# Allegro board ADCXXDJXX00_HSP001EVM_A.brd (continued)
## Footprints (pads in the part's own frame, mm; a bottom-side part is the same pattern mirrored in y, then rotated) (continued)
DBV5
  rect 1.27x0.508 smd: 1(-1.1,0.95) 2(-1.1,0) 3(-1.1,-0.95) 4(1.1,-0.95) 5(1.1,0.95)
DIODE_MBRB2515L
  rect 3.048x1.016 smd: 1(5.652,-2.54) 3(5.652,2.54)
  round 0.013 smd: 2(5.652,0)
  rect 8.382x10.668 smd: 4(-5.652,0)
DIODE_SM_1N4148W
  rect 0.889x0.94 smd: 1(-1.575,0) 2(1.575,0)
HDR_THVT_1X2_100_M
  rect 1.473x1.473 hole 0.965: 1(0,0)
  round 1.473 hole 0.965: 2(0,-2.54)
HDR_THVT_1X3_100_M
  rect 1.575x1.575 hole 1.016: 1(0,0)
  round 1.575 hole 1.016: 2(0,-2.54) 3(0,-5.08)
HDR_THVT_1X4_100_M
  rect 1.473x1.473 hole 0.965: 1(0,0)
  round 1.473 hole 0.965: 2(0,-2.54) 3(0,-5.08) 4(0,-7.62)
HDR_THVT_2X4_100_M
  rect 1.473x1.473 hole 0.965: 1(0,0)
  round 1.473 hole 0.965: 2(2.54,0) 3(0,-2.54) 4(2.54,-2.54) 5(0,-5.08) 6(2.54,-5.08) 7(0,-7.62) 8(2.54,-7.62)
IND_0603
  rect 0.635x1.016 smd: 1(-0.635,0) 2(0.635,0)
IND_SM_XFL4015
  rect 0.991x3.404 smd: 1(-1.181,0) 2(1.181,0)
LED_0603
  rect 0.762x0.813 smd: 1(-0.787,0) 2(0.787,0)
LED_0805
  rect 1.422x1.524 smd: 1(-1.143,0) 2(1.143,0)
MFG125_PLATED
  round 3.556 hole 3.175: 1(0,0)
MSOP_8_118X118_0P65MM
  rect 1.45x0.46 smd: 1(-2.2,0.975) 2(-2.2,0.325) 3(-2.2,-0.325) 4(-2.2,-0.975) 5(2.2,-0.975) 6(2.2,-0.325) 7(2.2,0.325) 8(2.2,0.975)
PROBE_POINT_30PAD
  round 0.762 smd: 1(0,0)
QFN40_RTA_RTB_RHA
  custom 0.076x0.076 smd: 1(-3.025,2.25) 2(-3.025,1.75) 3(-3.025,1.25) 4(-3.025,0.75) 5(-3.025,0.25) 6(-3.025,-0.25) 7(-3.025,-0.75) 8(-3.025,-1.25) 9(-3.025,-1.75) 10(-3.025,-2.25) 11(-2.25,-3.025) 12(-1.75,-3.025) 13(-1.25,-3.025) 14(-0.75,-3.025) 15(-0.25,-3.025) 16(0.25,-3.025) 17(0.75,-3.025) 18(1.25,-3.025) 19(1.75,-3.025) 20(2.25,-3.025) 21(3.025,-2.25) 22(3.025,-1.75) 23(3.025,-1.25) 24(3.025,-0.75) 25(3.025,-0.25) 26(3.025,0.25) 27(3.025,0.75) 28(3.025,1.25) 29(3.025,1.75) 30(3.025,2.25) 31(2.25,3.025) 32(1.75,3.025) 33(1.25,3.025) 34(0.75,3.025) 35(0.25,3.025) 36(-0.25,3.025) 37(-0.75,3.025) 38(-1.25,3.025) 39(-1.75,3.025) 40(-2.25,3.025)
  rect 4.572x4.572 smd: 41(0,0)
QFN_7_2MMX2MM
  rect 0.6x0.25 smd: 1(-0.9,0.75)
  oval 0.6x0.25 smd: 2(-0.9,0.25) 3(-0.9,-0.25) 4(-0.9,-0.75)
  rect 1.5x0.3 smd: 5(0.45,-0.6) 6(0.45,0) 7(0.45,0.6)
QFN_20_197X197_0P65_RGW
  rect 0.991x0.356 smd: 1(-2.607,1.3) 2(-2.607,0.65) 3(-2.607,0) 4(-2.607,-0.65) 5(-2.607,-1.3) 11(2.607,-1.3) 12(2.607,-0.65) 13(2.607,0) 14(2.607,0.65) 15(2.607,1.3)
  rect 0.356x0.991 smd: 6(-1.3,-2.607) 7(-0.65,-2.607) 8(0,-2.607) 9(0.65,-2.607) 10(1.3,-2.607) 16(1.3,2.607) 17(0.65,2.607) 18(0,2.607) 19(-0.65,2.607) 20(-1.3,2.607)
  rect 3.15x3.15 smd: 21(0,0)
QFN_20_199X199_0P65MM
  rect 0.991x0.356 smd: 1(-2.4,1.3) 2(-2.4,0.65) 3(-2.4,0) 4(-2.4,-0.65) 5(-2.4,-1.3) 11(2.4,-1.3) 12(2.4,-0.65) 13(2.4,0) 14(2.4,0.65) 15(2.4,1.3)
  rect 0.356x0.991 smd: 6(-1.3,-2.4) 7(-0.65,-2.4) 8(0,-2.4) 9(0.65,-2.4) 10(1.3,-2.4) 16(1.3,2.4) 17(0.65,2.4) 18(0,2.4) 19(-0.65,2.4) 20(-1.3,2.4)
  rect 3.15x3.15 smd: 21(0,0)
QFN_64_0P50MM_RGC_FT2232HQ
  custom 0.076x0.076 smd: 1(-4.58,3.753) 2(-4.58,3.252) 3(-4.58,2.752) 4(-4.58,2.252) 5(-4.58,1.751) 6(-4.58,1.251) 7(-4.58,0.751) 8(-4.58,0.25) 9(-4.58,-0.25) 10(-4.58,-0.751) 11(-4.58,-1.251) 12(-4.58,-1.751) 13(-4.58,-2.252) 14(-4.58,-2.752) 15(-4.58,-3.252) 16(-4.58,-3.753) 17(-3.753,-4.58) 18(-3.252,-4.58) 19(-2.752,-4.58) 20(-2.252,-4.58) 21(-1.751,-4.58) 22(-1.251,-4.58) 23(-0.751,-4.58) 24(-0.25,-4.58) 25(0.25,-4.58) 26(0.751,-4.58) 27(1.251,-4.58) 28(1.751,-4.58) 29(2.252,-4.58) 30(2.752,-4.58) 31(3.252,-4.58) 32(3.753,-4.58) 33(4.58,-3.753) 34(4.58,-3.252) 35(4.58,-2.752) 36(4.58,-2.252) 37(4.58,-1.751) 38(4.58,-1.251) 39(4.58,-0.751) 40(4.58,-0.25) 41(4.58,0.25) 42(4.58,0.751) 43(4.58,1.251) 44(4.58,1.751) 45(4.58,2.252) 46(4.58,2.752) 47(4.58,3.252) 48(4.58,3.753) 49(3.753,4.58) 50(3.252,4.58) 51(2.752,4.58) 52(2.252,4.58) 53(1.751,4.58) 54(1.251,4.58) 55(0.751,4.58) 56(0.25,4.58) 57(-0.25,4.58) 58(-0.751,4.58) 59(-1.251,4.58) 60(-1.751,4.58) 61(-2.252,4.58) 62(-2.752,4.58) 63(-3.252,4.58) 64(-3.753,4.58)
  rect 4.318x4.318 smd: 65(0,0)
QFN_64_360X360_0P50MM_PWRPAD
  oval 1.016x0.305 smd: 1(-4.58,3.753) 2(-4.58,3.252) 3(-4.58,2.752) 4(-4.58,2.252) 5(-4.58,1.751) 6(-4.58,1.251) 7(-4.58,0.751) 8(-4.58,0.25) 9(-4.58,-0.25) 10(-4.58,-0.751) 11(-4.58,-1.251) 12(-4.58,-1.751) 13(-4.58,-2.252) 14(-4.58,-2.752) 15(-4.58,-3.252) 16(-4.58,-3.753) 33(4.58,-3.753) 34(4.58,-3.252) 35(4.58,-2.752) 36(4.58,-2.252) 37(4.58,-1.751) 38(4.58,-1.251) 39(4.58,-0.751) 40(4.58,-0.25) 41(4.58,0.25) 42(4.58,0.751) 43(4.58,1.251) 44(4.58,1.751) 45(4.58,2.252) 46(4.58,2.752) 47(4.58,3.252) 48(4.58,3.753)
  oval 0.305x1.016 smd: 17(-3.753,-4.58) 18(-3.252,-4.58) 19(-2.752,-4.58) 20(-2.252,-4.58) 21(-1.751,-4.58) 22(-1.251,-4.58) 23(-0.751,-4.58) 24(-0.25,-4.58) 25(0.25,-4.58) 26(0.751,-4.58) 27(1.251,-4.58) 28(1.751,-4.58) 29(2.252,-4.58) 30(2.752,-4.58) 31(3.252,-4.58) 32(3.753,-4.58) 49(3.753,4.58) 50(3.252,4.58) 51(2.752,4.58) 52(2.252,4.58) 53(1.751,4.58) 54(1.251,4.58) 55(0.751,4.58) 56(0.25,4.58) 57(-0.25,4.58) 58(-0.751,4.58) 59(-1.251,4.58) 60(-1.751,4.58) 61(-2.252,4.58) 62(-2.752,4.58) 63(-3.252,4.58) 64(-3.753,4.58)
  rect 7.366x7.366 smd: 65(0,0)
SMA_SMEL_373X312
  rect 0.635x5.08 smd: 1(0,-2.54)
  rect 2.286x5.08 smd: 2(-4.445,-2.54) 3(4.445,-2.54) 4(-4.445,-2.54) 5(4.445,-2.54)
SMA_THVT_312X312
  round 2.337 hole 1.575: 1(0,0)
  round 2.464 hole 1.702: 2(-2.54,2.54) 3(2.54,2.54) 4(2.54,-2.54) 5(-2.54,-2.54)
SMA_THVT_SMT_250X250
  round 0.787 smd: 1(0,0)
  round 1.829 hole 1.499: 2(-2.54,-2.54) 3(2.54,-2.54) 4(2.54,2.54) 5(-2.54,2.54)
SMD_JUMPER_L_0402
  rect 0.508x0.508 smd: 1(-0.508,0) 2(0.508,0) 3(0.508,1.016)
SMP_B120
  rect 0.508x1.321 smd: 1(0,-3.1)
  custom 1.3x1.3 smd: 2(0,0)
SO_8_207X207_50
  rect 1.702x0.66 smd: 1(-3.645,1.905) 2(-3.645,0.635) 3(-3.645,-0.635) 4(-3.645,-1.905) 5(3.645,-1.905) 6(3.645,-0.635) 7(3.645,0.635) 8(3.645,1.905)
SOIC_8_197X157_50
  rect 2.159x0.61 smd: 1(-2.44,1.905) 2(-2.44,0.635) 3(-2.44,-0.635) 4(-2.44,-1.905) 5(2.44,-1.905) 6(2.44,-0.635) 7(2.44,0.635) 8(2.44,1.905)
SON_Q5B_8
  rect 1.372x0.711 smd: 1(-2.767,1.905) 2(-2.767,0.635) 3(-2.767,-0.635) 4(-2.767,-1.905) 5(2.767,-1.905) 6(2.767,-0.635) 7(2.767,0.635) 8(2.767,1.905)
SOT_5_120X69_37
  rect 0.61x1.524 smd: 1(-0.95,-1.75) 2(0,-1.75) 3(0.95,-1.75) 4(0.95,1.75) 5(-0.95,1.75)
SOT_5_120X69_57
  rect 0.61x1.524 smd: 1(-0.95,-1.35) 2(0,-1.35) 3(0.95,-1.35) 4(0.95,1.35) 5(-0.95,1.35)
SOT_23_MMBT3904
  rect 0.991x1.397 smd: 1(-0.953,-1.105) 2(0.953,-1.105) 3(0,1.105)
TANT_B
  rect 2.032x2.286 smd: 1(-1.524,0) 2(1.524,0)
TFMR_5_150X150_50
  rect 1.651x0.762 smd: 1(1.587,1.27) 2(1.587,0) 3(1.587,-1.27) 4(-1.587,-1.27) 6(-1.587,1.27)
TP_THVT_100_RND
  round 2.54 hole 1.016: 1(0,0)
TP_THVT_125_RND_063D
  round 2.362 hole 1.6: 1(0,0)
TSSOP_16_201X177_26
  rect 1.6x0.35 smd: 1(-2.825,2.275) 2(-2.825,1.625) 3(-2.825,0.975) 4(-2.825,0.325) 5(-2.825,-0.325) 6(-2.825,-0.975) 7(-2.825,-1.625) 8(-2.825,-2.275) 9(2.825,-2.275) 10(2.825,-1.625) 11(2.825,-0.975) 12(2.825,-0.325) 13(2.825,0.325) 14(2.825,0.975) 15(2.825,1.625) 16(2.825,2.275)
unnamed#2
  round 1.016 smd: 1(0,0)
unnamed#3
  round 0.762 smd: (0,0)
VCXO_6_CUSTOM
  rect 5.74x1.956 smd: 1(-3.81,2.54) 2(-3.81,0) 3(-3.81,-2.54) 4(3.81,-2.54) 5(3.81,0) 6(3.81,2.54)
WSON_14_4MMX4MM_0P5
  rect 0.61x0.254 smd: 1(-1.9,1.5) 2(-1.9,1) 3(-1.9,0.5) 4(-1.9,0) 5(-1.9,-0.5) 6(-1.9,-1) 7(-1.9,-1.5) 8(1.9,-1.5) 9(1.9,-1) 10(1.9,-0.5) 11(1.9,0) 12(1.9,0.5) 13(1.9,1) 14(1.9,1.5)
  rect 2.6x3 smd: 15(0,0)
XTAL_2_SM_126X197
  rect 1.9x2.4 smd: 1(-2.05,0) 2(2.05,0)

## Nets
1.4V: C211.1 C212.1 C213.1 L4.2 R158.2 R160.1 R164.1 R167.2 SJP3.1(PIN1) SJP4.1(PIN1) TP17.1 U17.4(VOS) U20.5(IN1) U20.6(IN2) U20.7(IN3) U20.8(IN4)
5.0V_IN: D13.4 F1.1 J37.1 Q3.5(D5) Q3.6(D6) Q3.7(D7) Q3.8(D8) TP12.1(TP) U13.5(VIN)
5VIN: C196.1 C198.1 C209.1 C215.1 C225.1 C238.1 F1.2 Q3.1(S1) Q3.2(S2) Q3.3(S3) R148.1 U14.1(EN) U14.7(IN) U17.1(EN) U17.7(IN) U21.13(EN) U21.15(IN2) U21.16(IN1) U22.13(EN) U22.15(IN2) U22.16(IN1)
+2.2V: C206.1 C207.1 C208.1 C210.1 L3.2 R150.1 R152.1 SJP2.1(PIN1) SJP3.3(PIN3) TP15.1(TP) U14.4(VOS) U16.15(IN3) U16.16(IN2) U16.17(IN1)
+3.3V_LMX: C100.1 C101.1 C102.2 C103.1 C106.1 C107.2 C113.1 C114.2 C242.1 C243.1 C244.1 C245.1 FB22.2 R46.2 TP24.1 U3.7(VCCDIG) U3.11(VCCCP) U3.15(VCCDIV) U3.21(VCCBUF) U3.26(VCCDBLR) U3.37(VCCVCO)
+3.3V_LMXRF: C99.1 C105.1 C247.1 C248.1 FB23.2 R44.2 R45.2 R48.2 R49.2 TP27.1
+3.3VCLK: C229.1 C230.1 C233.1 C234.1 FB1.2 FB2.1 FB3.1 FB4.1 FB5.1 FB6.1 FB10.1 FB11.1 FB20.2 R82.1 R88.1 R96.2 SJP1.3(PIN3) TP22.1
GND: C1.2 C2.2 C3.1 C4.1 C14.1 C24.1 C41.2 C42.2 C43.2 C54.2 C55.2 C56.2 C57.2 C58.2 C59.2 C60.2 C61.2 C62.2 C63.2 C64.2 C65.2 C66.2 C67.2 C68.2 C69.2 C70.2 C71.2 C72.2 C73.2 C74.2 C75.2 C76.2 C77.2 C78.2 C79.2 C80.2 C81.2 C82.2 C83.2 C84.2 C85.2 C86.2 C87.2 C88.2 C89.2 C90.2 C91.2 C92.2 C93.2 C94.2 C95.2 C96.2 C99.2 C100.2 C101.2 C102.1 C103.2 C104.1 C105.2 C106.2 C107.1 C109.2 C111.1 C112.1 C113.2 C114.1 C115.1 C116.1 C117.1 C118.1 C119.2 C121.2 C122.2 C130.2 C132.2 C137.1 C138.1 C139.1 C140.1 C141.1 C146.1 C152.1 C154.1 C155.1 C156.1 C157.2 C158.2 C159.2 C160.1 C161.1 C162.1 C163.2 C164.2 C165.2 C166.2 C167.1 C168.2 C169.2 C170.2 C171.2 C172.2 C173.2 C174.2 C175.2 C176.2 C177.2 C178.2 C179.2 C180.2 C181.2 C182.2 C183.2 C184.2 C185.2 C186.2 C187.2 C188.2 C189.2 C190.2 C191.2 C192.2 C193.2 C194.2 C195.2 C196.2 C198.2 C200.2 C201.2 C202.2 C203.2 C204.2 C205.2 C206.2 C207.2 C208.2 C209.2 C210.2 C211.2 C212.2 C213.2 C214.2 C215.2 C217.2 C218.2 C219.2 C220.2 C221.2 C222.2 C223.2 C224.2 C225.2 C226.2 C227.2 C228.2 C229.2 C230.2 C233.2 C234.2 C235.2 C236.2 C237.2 C238.2 C239.2 C240.2 C241.2 C242.2 C243.2 C244.2 C245.2 C246.2 C247.2 C248.2 D2.2(CATHODE) D3.2(CATHODE) D4.2(CATHODE) D5.2(CATHODE) D6.2(CATHODE) D8.2(CATHODE) D13.1 D13.3 FB16.2 FB17.2 FB18.2 FB19.2 J1.2(SHIELD1) J1.3(SHIELD2) J1.4(SHIELD3) J1.5(SHIELD4) J2.2(GND#2) J2.3(GND#3) J2.4(GND#4) J2.5(GND#5) J3.2(SHIELD1) J3.3(SHIELD2) J3.4(SHIELD3) J3.5(SHIELD4) J4.2(SHIELD1) J4.3(SHIELD2) J4.4(SHIELD3) J4.5(SHIELD4) J5.2(GND#2) J5.3(GND#3) J5.4(GND#4) J5.5(GND#5) J6.2(SHIELD1) J6.3(SHIELD2) J6.4(SHIELD3) J6.5(SHIELD4) J14.2(GND#2) J14.3(GND#3) J14.4(GND#4) J14.5(GND#5) J15.2(GND#2) J15.3(GND#3) J15.4(GND#4) J15.5(GND#5) J18.2(GND#2) J18.3(GND#3) J18.4(GND#4) J18.5(GND#5) J20.2(SHIELD1) J22.2(GND#2) J22.3(GND#3) J22.4(GND#4) J22.5(GND#5) J23.2(SHIELD1) J23.3(SHIELD2) J23.4(SHIELD3) J23.5(SHIELD4) J24.2(SHIELD1) J24.3(SHIELD2) J24.4(SHIELD3) J24.5(SHIELD4) J25.A1 J25.A4 J25.A5 J25.A8 J25.A9 J25.A12 J25.A13 J25.A16 J25.A17 J25.A20 J25.A24 J25.A25 J25.A28 J25.A29 J25.A32 J25.A33 J25.A36 J25.A37 J25.A40 J25.B3 J25.B6 J25.B7 J25.B10 J25.B11 J25.B14 J25.B15 J25.B18 J25.B26 J25.B27 J25.B30 J25.B31 J25.B34 J25.B35 J25.B38 J25.B39 J25.C5 J25.C8 J25.C24 J25.C25 J25.C28 J25.C29 J25.C32 J25.C33 J25.C36 J25.C38 J25.C40 J25.D3 J25.D6 J25.D25 J25.D28 J25.D37 J25.D39 J25.E26 J25.E29 J25.E32 J25.E35 J25.E38 J25.E40 J25.F27 J25.F30 J25.F33 J25.F36 J25.F39 J25.G5 J25.G8 J25.G11 J25.G14 J25.G26 J25.G29 J25.G32 J25.G35 J25.G38 J25.G40 J25.H27 J25.H30 J25.H33 J25.H36 J25.H39 J25.J29 J25.J32 J25.J35 J25.J38 J25.J40 J25.K30 J25.K33 J25.K36 J25.K39 J25.L30 J25.L31 J25.L34 J25.L35 J25.L38 J25.L39 J25.M1 J25.M29 J25.M32 J25.M33 J25.M36 J25.M37 J25.M40 J25.Y4 J25.Y5 J25.Y8 J25.Y9 J25.Y12 J25.Y13 J25.Y16 J25.Y17 J25.Y20 J25.Y21 J25.Y24 J25.Y25 J25.Y28 J25.Y29 J25.Y32 J25.Y33 J25.Y36 J25.Y37 J25.Y40 J25.Z2 J25.Z3 J25.Z7 J25.Z10 J25.Z11 J25.Z14 J25.Z15 J25.Z18 J25.Z19 J25.Z22 J25.Z23 J25.Z26 J25.Z27 J25.Z30 J25.Z31 J25.Z34 J25.Z35 J25.Z38 J25.Z39 J28.3 J31.5(GND) J31.6(GND1) J31.7(GND2) J31.8(GND3) J31.9(GND4) J37.2 J37.3 J38.2(GND#2) J38.3(GND#3) J38.4(GND#4) J38.5(GND#5) JP5.1 JP7.2 JP8.2 JP9.2 MT1.1 MT2.1 R11.2 R12.2 R17.2 R18.2 R21.2 R23.2 R26.2 R31.2 R32.2 R33.2 R51.1 R52.1 R53.1 R56.2 R57.2 R58.2 R61.2 R62.2 R63.2 R64.2 R65.2 R66.2 R68.2 R71.2 R72.2 R74.2 R75.2 R78.2 R79.2 R80.2 R81.2 R84.2 R85.2 R86.2 R87.2 R89.2 R90.2 R92.2 R93.2 R94.2 R95.2 R99.2 R106.2 R108.2 R109.2 R122.1 R153.2 R154.1 R155.1 R156.1 R157.1 R166.2 R168.2 R169.2 R170.1 R171.1 R172.1 R173.1 R174.1 R175.1 R176.1 R177.1 R183.1 R184.2 R185.2 R187.2 R188.2 R189.2 SJP1.1(PIN1) SJP2.3(PIN3) T1.2(SECONDARY_CT) T1.4(PRIMARY) T2.4(PRIMARY) TP13.1(TP) TP16.1(TP) TP18.1(TP) TP21.1(TP) TP28.1(TP) TP29.1(TP) TP30.1(TP) U1.A1(AGND#A1) U1.A2(AGND#A2) U1.A3(AGND#A3) U1.A6(AGND#A6) U1.A7(AGND#A7) U1.A12(DGND#A12) U1.B2(AGND#B2) U1.B3(AGND#B3) U1.B4(AGND#B4) U1.B5(AGND#B5) U1.B6(AGND#B6) U1.B7(AGND#B7) U1.B12(DGND#B12) U1.C6(AGND#C6) U1.D1(AGND#D1) U1.D6(AGND#D6) U1.D9(DGND#D9) U1.D10(DGND#D10) U1.E1(AGND#E1) U1.E6(AGND#E6) U1.F2(AGND#F2) U1.F3(AGND#F3) U1.F6(AGND#F6) U1.F9(DGND#F9) U1.F10(DGND#F10) U1.G2(AGND#G2) U1.G3(AGND#G3) U1.G6(AGND#G6) U1.G9(DGND#G9) U1.G10(DGND#G10) U1.H1(AGND#H1) U1.H6(AGND#H6) U1.J1(AGND#J1) U1.J6(AGND#J6) U1.J9(DGND#J9) U1.J10(DGND#J10) U1.L2(AGND#L2) U1.L3(AGND#L3) U1.L4(AGND#L4) U1.L5(AGND#L5) U1.L6(AGND#L6) U1.L7(AGND#L7) U1.L12(DGND#L12) U1.M1(AGND#M1) U1.M2(AGND#M2) U1.M3(AGND#M3) U1.M6(AGND#M6) U1.M7(AGND#M7) U1.M12(DGND#M12) U2.8(GND) U2.9(A0) U2.15(PWRPAD) U3.2(GND#2) U3.4(GND#4) U3.6(GND#6) U3.13(GND#13) U3.14(GND#14) U3.25(GND#25) U3.31(GND#31) U3.34(GND#34) U3.39(GND#39) U3.40(NC4) U3.41(PWRPAD) U4.65(DAP) U5.3(A2) U5.4(VSS) U6.2(GND) U7.3(GND) U8.1(GND#1) U8.5(GND#5) U8.10(AGND) U8.11(GND#11) U8.13(TEST) U8.15(GND#15) U8.25(GND#25) U8.35(GND#35) U8.47(GND#47) U8.51(GND#51) U8.65(PWRPAD) U9.5(VSS) U10.7(DIR3) U10.10(GND) U11.10(GND) U12.1(DIR1) U12.2(DIR2) U12.7(DIR3) U12.8(DIR4) U12.10(GND) U13.2(GND) U14.5(GND) U15.4(V-) U16.8(GND1) U16.18(GND2) U16.21(PWRPAD) U17.5(GND) U20.2(NC1) U20.3(NC2) U20.4(NC3) U20.12(GND) U20.13(NC4) U20.14(NC5) U20.17(NC6) U20.21(PAD) U21.7(GND) U21.21(PWRPAD) U22.7(GND) U22.21(PWRPAD) Y1.3(GND)
V3P3V: C226.1 C227.1 C228.1 FB20.1 FB21.1 U21.1(OUT1) U21.3(SENSE) U21.20(OUT2)
V3P3V_LMX: C239.1 C240.1 C241.1 FB22.1 FB23.1 U22.1(OUT1) U22.3(SENSE) U22.20(OUT2)
V11_OUT: C214.1 C216.1 C217.1 R161.1 R163.2 R165.1 U20.1(OUT1) U20.18(OUT2) U20.19(OUT3) U20.20(OUT4)
V19_SNS: FB16.1 FB17.1 R149.1 U16.1(OUT1) U16.2(SNS) U16.19(OUT2) U16.20(OUT3)
VBUS: C175.1 R111.1 U6.1(IN) U6.3(EN)
VBUSS: C173.1 FB14.1 U6.5(OUT)
VCCIN: C104.2 U3.10(VCCIN)
VDDD33: C1.1 C2.1 C41.1 C42.1 C43.1 C172.1 C180.1 C186.1 C187.1 C188.1 C189.1 C190.1 C192.1 C194.1 C236.1 C237.1 D1.1(ANODE) D7.1(ANODE) FB12.1 FB13.1 FB21.2 JP6.1(PIN1) R27.1 R28.1 R29.1 R30.1 R39.1 R41.1 R114.1 R115.1 R123.1 R124.1 R125.1 R130.1 TP23.1 U2.2(VDD) U7.5(VCC) U8.20(VCCIO#20) U8.31(VCCIO#31) U8.42(VCCIO#42) U8.56(VCCIO#56) U9.8(VCC) U10.1(DIR1) U10.2(DIR2) U10.8(DIR4) U10.16(VCCA) U11.1(DIR1) U11.2(DIR2) U11.7(DIR3) U11.8(DIR4) U11.16(VCCA) U12.16(VCCA) U15.8(V+)
VDDL19: C191.1 C193.1 C195.1 C200.1 C201.1 FB16.3 R132.1 TP11.1 U10.15(VCCB) U11.15(VCCB) U12.15(VCCB)
VINA: BALUN1.1(IN) J2.1(CENTER)
VINB: BALUN2.1(IN) J5.1(CENTER)
1P4V: L4.1 U17.6(SW)
1P8V_USB: C178.1 C179.1 C181.1 C182.1 C183.1 TP10.1 U8.12(VCORE#12) U8.37(VCORE#37) U8.49(VREGOUT) U8.64(VCORE#64)
2: D13.2
2P2V: L3.1 U14.6(SW)
3P3USB: C170.1 C171.1 FB13.2 TP7.1 U8.9(VPLL)
3P3V_RX: R105.2 TP5.1
3P3VAUX: C167.2 J25.D32 J28.4 U5.8(VCC)
12P0V_RX: J25.C35 J25.C37
ADBUS0: U8.16(ADBUS0) U10.3(A1)
ADBUS1: U8.17(ADBUS1) U10.4(A2)
ADBUS2: U8.18(ADBUS2) U10.5(A3)
ADBUS3: U8.19(ADBUS3) U10.6(A4)
ADC_CLK: R133.2 U1.F8(SCLK)
ADC_SCSB: R136.2 U1.E8(\\S\C\S\)
ADC_SDI: R134.2 U1.G8(SDI)
ADC_SDO: R135.2 U1.H8(SDO)
BDBUS0: R112.1 U8.26(BDBUS0)
BDBUS1: U7.2(A) U8.27(BDBUS1)
BDBUS2: R113.1 U8.28(BDBUS2)
BDBUS3: U7.1(O\E\) U8.29(BDBUS3)
BYPASS: FB18.1 FB19.1 R159.1 R163.1
CALTRG: J9.2 R23.1 U1.E7(CALTRG)
CDBUS0: R118.1 U8.38(CDBUS0)
CDBUS1: R119.1 U8.39(CDBUS1)
CDBUS2: R115.2 R120.1 U8.40(CDBUS2)
CDBUS3: R114.2 R121.1 U8.41(CDBUS3)
CE: JP5.2 R46.1 U3.1(CE)
CLK+: C49.1 R43.2 T2.1(SECONDARY_DOT)
CLK-: C52.1 R43.1 T2.3(SECONDARY)
CLK-IN: R67.1 R69.1 R70.2 R72.1 T1.6(PRIMARY_DOT)
CLK_+: C48.2 C49.2 C50.2 U1.F1(CLK+)
CLK_-: C51.2 C52.2 C53.2 U1.G1(CLK-)
CLKIN0: J38.1(CENTER) R186.1 R187.1
CLKIN0_N: C24.2 U4.38(CLKIN0N)
CLKIN0_P: C20.2 U4.37(CLKIN0P)
CLKIN1: C20.1 R186.2
CLKIN1_N: C136.2 C137.2 U4.35(CLKIN1N/FBCLKINN/FINN)
CLKIN1_P: C134.2 U4.34(CLKIN1P/FBCLKINP/FINP)
CLKINN: C136.1 R73.2 T1.3(SECONDARY)
CLKINP: C134.1 R68.1 R69.2 R73.1 T1.1(SECONDARY_DOT)
CLKLA_0N: R90.1 R127.1 U4.63(DCLKOUT12N)
CLKLA_0P: R89.1 R126.1 U4.62(DCLKOUT12P)
CLKM: C53.1 C135.2
CLKP: C48.1 C133.2
CP1: C128.1 C130.1 U4.32(CPOUT1) Y1.1(VC)
CP2: C131.1 C132.1 U4.46(CPOUT2)
CPOUT: C119.1 C120.1 R54.1 U3.12(CPOUT)
DA0+: C5.1 U1.E12(DA0+)
DA0-: C6.1 U1.F12(DA0-)
DA0_M: C6.2 J25.A11
DA0_P: C5.2 J25.A10
DA1+: C7.1 U1.C12(DA1+)
DA1-: C8.1 U1.D12(DA1-)
DA1_M: C8.2 J25.C7
DA1_P: C7.2 J25.C6
DA2+: C9.1 U1.A10(DA2+)
DA2-: C10.1 U1.A11(DA2-)
DA2_M: C10.2 J25.A7
DA2_P: C9.2 J25.A6
DA3+: C11.1 U1.A8(DA3+)
DA3-: C12.1 U1.A9(DA3-)
DA3_M: C12.2 J25.A3
DA3_P: C11.2 J25.A2
DA4+: C13.1 U1.E11(DA4+)
DA4-: C15.1 U1.F11(DA4-)
DA4_M: C15.2 J25.Y15
DA4_P: C13.2 J25.Y14
DA5+: C16.1 U1.C11(DA5+)
DA5-: C18.1 U1.D11(DA5-)
DA5_M: C18.2 J25.Y11
DA5_P: C16.2 J25.Y10
DA6+: C19.1 U1.B10(DA6+)
DA6-: C21.1 U1.B11(DA6-)
DA6_M: C21.2 J25.B9
DA6_P: C19.2 J25.B8
DA7+: C22.1 U1.B8(DA7+)
DA7-: C23.1 U1.B9(DA7-)
DA7_M: C23.2 J25.B5
DA7_P: C22.2 J25.B4
DB0+: C25.1 U1.H12(DB0+)
DB0-: C26.1 U1.G12(DB0-)
DB0_M: C26.2 J25.B12
DB0_P: C25.2 J25.B13
DB1+: C27.1 U1.K12(DB1+)
DB1-: C28.1 U1.J12(DB1-)
DB1_M: C28.2 J25.A14
DB1_P: C27.2 J25.A15
DB2+: C29.1 U1.M10(DB2+)
DB2-: C30.1 U1.M11(DB2-)
DB2_M: C30.2 J25.B16
DB2_P: C29.2 J25.B17
DB3+: C31.1 U1.M8(DB3+)
DB3-: C32.1 U1.M9(DB3-)
DB3_M: C32.2 J25.A18
DB3_P: C31.2 J25.A19
DB4+: C33.1 U1.H11(DB4+)
DB4-: C34.1 U1.G11(DB4-)
DB4_M: C34.2 J25.Z12
DB4_P: C33.2 J25.Z13
DB5+: C35.1 U1.K11(DB5+)
DB5-: C36.1 U1.J11(DB5-)
DB5_M: C36.2 J25.Z16
DB5_P: C35.2 J25.Z17
DB6+: C37.1 U1.L10(DB6+)
DB6-: C38.1 U1.L11(DB6-)
DB6_M: C38.2 J25.Y18
DB6_P: C37.2 J25.Y19
DB7+: C39.1 U1.L8(DB7+)
DB7-: C40.1 U1.L9(DB7-)
DB7_M: C40.2 J25.Y22
DB7_P: C39.2 J25.Y23
DCLKOUT2_N: C135.1 R75.1 U4.16(DCLKOUT2N)
DCLKOUT2_P: C133.1 R74.1 U4.15(DCLKOUT2P)
DCLKOUT6_N: C153.1 R95.1 U4.28(DCLKOUT6N)
DCLKOUT6_P: C151.1 R94.1 U4.27(DCLKOUT6P)
DCLKOUT8_N: R24.1 R57.1 U4.52(DCLKOUT8N)
DCLKOUT8_P: R22.1 R58.1 U4.51(DCLKOUT8P)
DCLKOUT10_N: C143.2 J24.1(CENTER)
DCLKOUT10_P: C142.2 J23.1(CENTER)
DCLKOUT10N: C143.1 R87.1 U4.55(DCLKOUT10N)
DCLKOUT10P: C142.1 R86.1 U4.54(DCLKOUT10P)
DDBUS0: U8.48(DDBUS0) U11.3(A1)
DDBUS1: U8.52(DDBUS1) U11.4(A2)
DDBUS2: U8.53(DDBUS2) U11.5(A3)
DDBUS3: U8.54(DDBUS3) U11.6(A4)
DDBUS4: U8.55(DDBUS4) U12.3(A1)
DDBUS5: U8.57(DDBUS5) U12.4(A2)
DDBUS6: U8.58(DDBUS6) U12.5(A3)
DDBUS7: U8.59(DDBUS7) U12.6(A4)
DEVCLKIN: J18.1(CENTER) T2.6(PRIMARY_DOT)
DM: R116.2 U8.7(DM)
DP: R117.2 U8.8(DP)
EE_ADDR0_RX: J25.C34 U5.1(A0)
EE_ADDR1_RX: J25.D35 U5.2(A1)
EECLK: R124.2 U8.62(EECLK) U9.2(CLK)
EECS: R125.2 U8.63(EECS) U9.1(CS)
EEDATA: R131.1 U8.61(EEDATA) U9.3(DI)
FMC_SCL: J25.C30 J28.2 U5.6(SCL)
FMC_SDA: J25.C31 J28.1 U5.5(SDA)
FPGA_JESD_CLK_A_N: J25.D5 R129.2
FPGA_JESD_CLK_A_P: J25.D4 R128.2
FPGA_JESD_CLK_B_N: J25.G7 R127.2
FPGA_JESD_CLK_B_P: J25.G6 R126.2
FPGA_JESD_CLK_C_N: J25.Z21 R24.2
FPGA_JESD_CLK_C_P: J25.Z20 R22.2
FPGA_JESD_SYSREFM: J25.G10 R60.2
FPGA_JESD_SYSREFP: J25.G9 R59.2
GTXCLKM: R64.1 R129.1 U4.2(DCLKOUT0N)
GTXCLKP: R65.1 R128.1 U4.1(DCLKOUT0P)
HSPC_PRSNT_M2C_L: J25.Z1 J30.1
INA+: BALUN1.3(O1) R1.1
INA-: BALUN1.2(O2) R4.1
INA_+: J1.1(CENTER) R180.1
INA_-: J3.1(CENTER) R179.1
INAN: R4.2 R179.2 U1.A5(INA-)
INAP: R1.2 R180.2 U1.A4(INA+)
INB+: BALUN2.2(O2) R6.1
INB-: BALUN2.3(O1) R9.1
INB_+: J4.1(CENTER) R151.1
INB_-: J6.1(CENTER) R162.1
INBN: R9.2 R162.2 U1.M5(INB-)
INBP: R6.2 R151.2 U1.M4(INB+)
JESD_SYSREFM: R60.1 R61.1 U4.4(SDCLKOUT1N)
JESD_SYSREFP: R59.1 R62.1 U4.3(SDCLKOUT1P)
LM95233_SMBCLK: R41.2 R112.2 U2.13(SMBCLK)
LM95233_SMBDAT: R39.2 R110.2 R113.2 U2.12(SMBDAT)
LMK04828_CSB: R120.2 TP36.1(TP) U4.18(\\C\S\)
LMK04828_SYNC: J25.J15 R97.2
LMK LOCKED: D5.1(ANODE) R102.1
LMK_CLKIN: J22.1(CENTER) R70.1 R71.1
LMK_LMX_CLK: R118.2 U3.16(SCK) U4.19(SCK)
LMK_LMX_DATA: R119.2 U3.17(SDI) U4.20(SDIO)
LMK_SDO: R99.1 R178.2 U4.5(RESET)
LMX_CLKB: C108.2 R52.2 R67.2
LMX_CLKM: C51.1 R45.1 U3.22(RFOUTAM)
LMX_CLKP: C50.1 R44.1 U3.23(RFOUTAP)
LMX_CSB: R121.2 U3.24(CSB)
LMX_OSCM: C151.2 C249.1 U3.9(OSCINM)
LMX_OSCP: C153.2 C250.1 U3.8(OSCINP)
LMX_SDO: R47.2 U8.43(CDBUS4)
MUX_OUT: R47.1 R50.2 U3.20(MUXOUT)
NCOA0: J7.2 R11.1 R138.2 U1.C7(NCOA0)
NCOA1: J7.4 R12.1 R139.2 U1.D7(NCOA1)
NCOB0: J7.6 R17.1 R140.2 U1.K7(NCOB0)
NCOB1: J7.8 R18.1 R141.2 U1.J7(NCOB1)
OSC_M: C250.2 R188.1 U4.41(OSCOUTN)
OSC_P: C249.2 R189.1 U4.40(OSCOUTP)
OSCI: C184.1 U8.2(OSCI) Y2.2
OSCINN: C150.2 C152.2 U4.44(OSCINN)
OSCINP: C145.2 C146.2 U4.43(OSCINP)
OSCN: C149.2 C150.1 R88.2 R93.1
OSCO: C185.1 U8.3(OSCO) Y2.1
OSCP: C144.2 C145.1 R82.2 R85.1
OVRA0: D12.1(ANODE) J25.G27 R143.2 U1.C8(OVRA0)
OVRA1: R144.2 U1.D8(OVRA1)
OVRB0: D9.1(ANODE) J25.D26 R145.2 U1.K8(OVRB0)
OVRB1: R146.2 U1.J8(OVRB1)
PD: J8.2 R21.1 U1.K6(PD)
PG: R149.2 SJP4.3(PIN3) U16.4(PG)
PG_RX1: J25.F1 J26.2 R104.2
PLL2 LOCKED: D6.1(ANODE) R103.1
PRSNT_M2C_L: J25.H2 R106.1
RFOUTB_M: C110.1 R49.1 U3.19(RFOUTBM)
RFOUTB_P: C108.1 R48.1 U3.18(RFOUTBP)
RFOUTBM: C110.2 J20.1(CENTER) R53.2
STAT 0: D3.1(ANODE) R100.1
STAT 1: D4.1(ANODE) R101.1
SYNC: R96.1 R97.1 R98.1 TP4.1(TP) U4.6(SYNC)
SYNC_N: J25.G13 R36.1
SYNC_P: J25.G12 R35.1
SYNC_SE: J25.H31 R25.1 R98.2
SYNCSE: R25.2 R26.1 U1.C2(SYNC~_SE)
SYS+: C45.2 U1.K1(SYSREF+)
SYS-: C47.2 U1.L1(SYSREF-)
SYSREF+: R76.1 R78.1 U4.13(SDCLKOUT3P)
SYSREF-: R77.1 R79.1 U4.14(SDCLKOUT3N)
SYSREFM: C47.1 R77.2 R80.1
SYSREFP: C45.1 R76.2 R81.1
TCRIT1: R28.2 R37.2 TP1.1(TP) U2.10(\\T\C\R\I\T\1)
TCRIT2: R27.2 TP2.1(TP) U2.11(\\T\C\R\I\T\2)
TCRIT3: R29.2 TP3.1(TP) U2.14(\\T\C\R\I\T\3)
TDI: J25.D30 J27.1
TDIODE+: J17.2 R40.2 U1.K2(TDIODE+)
TDIODE-: J17.1 R42.2 U1.K3(TDIODE-)
TDIODEN: C44.2 C46.2 Q1.2(E) R42.1 U2.5(D-)
TDIODEP: C44.1 R40.1 U2.7(D1+)
TDO: J25.D31 J27.2
TMSP+: J14.1(CENTER) R34.1
TMSP-: J15.1(CENTER) R38.1
TMSTP+: R34.2 R35.2 U1.B1(TMSTP+)
TMSTP-: R36.2 R38.2 U1.C1(TMSTP-)
U19_BYPASS: R158.1 R159.2
V_BUS: C174.1 C177.1 FB14.2 JP6.3(PIN3)
VA11: C54.1 C55.1 C56.1 C57.1 C58.1 C59.1 C60.1 C61.1 C62.1 C63.1 C64.1 C65.1 C66.1 C67.1 C68.1 C218.1 C219.1 C220.1 FB18.3 TP19.1 TP31.1 U1.C5(VA11#C5) U1.D2(VA11#D2) U1.D3(VA11#D3) U1.D5(VA11#D5) U1.E5(VA11#E5) U1.F5(VA11#F5) U1.G5(VA11#G5) U1.H5(VA11#H5) U1.J2(VA11#J2) U1.J3(VA11#J3) U1.J5(VA11#J5) U1.K5(VA11#K5)
VA19: C69.1 C70.1 C71.1 C72.1 C73.1 C74.1 C75.1 C76.1 C77.1 C78.1 C79.1 C80.1 C81.1 C82.1 C83.1 C202.1 C203.1 C204.1 C205.1 FB17.3 R13.1 R14.1 R15.1 R16.1 R19.1 R20.1 TP14.1 TP32.1 U1.C4(VA19#C4) U1.D4(VA19#D4) U1.E2(VA19#E2) U1.E3(VA19#E3) U1.E4(VA19#E4) U1.F4(VA19#F4) U1.G4(VA19#G4) U1.H2(VA19#H2) U1.H3(VA19#H3) U1.H4(VA19#H4) U1.J4(VA19#J4) U1.K4(VA19#K4)
VADJ_RX: J25.E39 J25.F40 J25.G39 J25.H40 R104.1 R107.1 TP6.1
VBIAS_VCO: C116.2 U3.3(VBIASVCO)
VBIASBANK: C109.1 C111.2 U3.27(VBIASBANK)
VD11: C84.1 C85.1 C86.1 C87.1 C88.1 C89.1 C90.1 C91.1 C92.1 C93.1 C94.1 C95.1 C96.1 C222.1 C223.1 C224.1 FB19.3 TP20.1 TP33.1 U1.C9(VD11#C9) U1.C10(VD11#C10) U1.E9(VD11#E9) U1.E10(VD11#E10) U1.G7(VD11#G7) U1.H7(VD11#H7) U1.H9(VD11#H9) U1.H10(VD11#H10) U1.K9(VD11#K9) U1.K10(VD11#K10)
VIO_B_M2C_RX: J25.J39 J25.K40 R107.2
VPHY: C168.1 C169.1 FB12.2 U8.4(VPHY)
VREF_VCO1: C112.2 U3.29(VREFVCO#29)
VREF_VCO2: C115.2 U3.36(VREFVCO#36)
VREG_VCO: C117.2 U3.38(VREGVCO)
VREGIN: C176.1 JP6.2(PIN2) U8.50(VREGIN)
VTUNE: C122.1 R55.2 U3.35(VTUNE)
Y1_N: R91.1 R92.1 Y1.4(OUT_N)
Y1_P: R83.1 R84.1 Y1.5(OUT_P)
YO1_N: C149.1 R91.2
YO1_P: C144.1 R83.2
N18340257: D8.1(ANODE) R148.2
N19631466: C235.1 U21.14(NR)
N19631491: R173.2 U21.8(1P6V)
N19631493: R171.2 U21.11(0P2V)
N19631495: R170.2 U21.12(0P1V)
N19631505: R172.2 U21.10(0P4V)
N19884870: C138.2 C139.2 C140.2 C141.2 FB1.1 Y1.6(VDD)
N19884947: SJP1.2(PIN2) Y1.2(NC)
N19887754: FB8.2 U4.42(VCC8_OSCIN)
N19887756: C160.2 C161.2 C162.2 FB6.2 FB7.1 FB8.1 FB9.1 U4.47(VCC10_PLL2)
N19887760: C165.1 FB10.2 U4.53(VCC11_CG3)
N19887762: C166.1 FB11.2 U4.64(VCC12_CG0)
N19887789: R102.2 U4.31(STATUS_LD1)
N19887795: R103.2 U4.48(STATUS_LD2)
N19887804: R101.2 U4.59(CLKIN_SEL1)
N19887822: R100.2 U4.58(CLKIN_SEL0)
N19887828: C163.1 U4.12(LDOBYP2)
N19887830: C164.1 U4.11(LDOBYP1)
N19887836: C154.2 C155.2 C156.2 FB2.2 U4.10(VCC1_VCO) U4.33(VCC5_DIG) U4.36(VCC6_PLL1)
N19887876: FB7.2 U4.39(VCC7_OSCOUT)
N19887878: FB9.2 U4.45(VCC9_CP2)
N19887910: C158.1 FB4.2 U4.21(VCC3_SYSREF)
N19887912: C157.1 FB3.2 U4.17(VCC2_CG1)
N19887930: C159.1 FB5.2 U4.26(VCC4_CG2)
N19955835: Q3.4(G) U13.4(GATE)
N20042801: R155.2 U16.7(200MV)
N20043120: R154.2 U16.6(100MV)
N20043460: R156.2 U16.9(400MV)
N20043630: R157.2 U16.10(800MV)
N20101312: R152.2 R153.1 U14.3(FB)
N20101373: R150.2 U14.2(PG)
N20111831: R160.2 R166.1 U17.3(FB)
N20111884: R164.2 U17.2(PG)
N20113519: C216.2 R165.2 R169.1
N20150497: SJP2.2(PIN2) U16.14(EN)
N20151052: SJP3.2(PIN2) U20.10(BIAS)
N20220969: C246.1 U22.14(NR)
N20220990: R177.2 U22.8(1P6V)
N20220992: R175.2 U22.11(0P2V)
N20220994: R174.2 U22.12(0P1V)
N20221006: R176.2 U22.10(0P4V)
N20234062: C118.2 U3.33(VBIASVARAC)
N20239082: R51.2 U3.30(REXT)
N20251064: C120.2 R56.1
N20251377: C121.1 R54.2 R55.1
N20258125: D2.1(ANODE) R50.1
N20381922: R130.2 U8.14(RESET)
N20381931: R122.2 U8.6(REF)
N20382261: C221.1 U20.15(SS)
N20382558: R123.2 R131.2 U9.4(DO)
N20382827: J31.3(D+) R117.1
N20382847: J31.2(D-) R116.1
N20392160: J31.1(VBUS) R111.2
N20393078: D7.2(CATHODE) R109.1
N20399374: R161.2 R168.1 U20.16(FB/SNS)
N20400206: SJP4.2(PIN2) U20.11(EN)
N20442573: J7.1 R13.2
N20442576: J7.3 R14.2
N20442579: J7.5 R15.2
N20442582: J7.7 R16.2
N20446174: TP26.1(TP) U1.C3(BG)
N20447902: D1.2(CATHODE) R37.1
N20452911: C46.1 Q1.1(B) Q1.3(C) U2.6(D2+)
N20475697: R138.1 U11.14(B1)
N20475701: R139.1 U11.13(B2)
N20475713: R140.1 U11.12(B3)
N20475725: R141.1 U11.11(B4)
N20475883: R142.1 U11.9(OEB)
N20476138: JP8.1 R142.2
N20477206: R133.1 U10.14(B1)
N20477210: R134.1 U10.13(B2)
N20477222: R135.1 U10.12(B3)
N20477234: R132.2 R136.1 U10.11(B4)
N20477392: R137.1 U10.9(OEB)
N20477396: JP7.1 R137.2
N20478124: R110.1 U7.4(Y)
N20479286: R143.1 U12.14(B1)
N20479288: R144.1 U12.13(B2)
N20479290: R145.1 U12.12(B3)
N20479292: R146.1 U12.11(B4)
N20479340: R147.1 U12.9(OEB)
N20479396: JP9.1 R147.2
N20523656: TP25.1(TP) U1.F7(CALSTAT)
N20560674: J25.C39 J25.D36 J25.D38 J25.D40 R105.1
N20560927: J25.D1 J26.1
N20597236: J30.2 R108.1
N20599204: R183.2 U16.5(50MV)
N20601243: D10.1(ANODE) U15.7(OUTB)
N20601382: D11.1(ANODE) U15.1(OUTA)
N20601403: D10.2(CATHODE) R185.1
N20601859: D11.2(CATHODE) R32.1
N20602433: C14.2 D9.2(CATHODE) R184.1 U15.5(INB+)
N20603216: C3.2 D12.2(CATHODE) R31.1 U15.3(INA+)
N20603624: C4.2 R30.2 R33.1 U15.2(INA-) U15.6(INB-)
N20606076: J9.1 R20.2
N20606250: J8.1 R19.2
N20733419: R178.1 U8.44(CDBUS5)
N198851401: C131.2 R66.1
N198852420: C128.2 R63.1
N2037970112: R167.1 U20.9(PG)

Pads without a net: J25 A21 A22 A23 A26 A27 A30 A31 A34 A35 A38 A39 B1 B2 B19 B20 B21 B22 B23 B24 B25 B28 B29 B32 B33 B36 B37 B40 C1 C2 C3 C4 C9 C10 C11 C12 C13 C14 C15 C16 C17 C18 C19 C20 C21 C22 C23 C26 C27 D2 D7 D8 D9 D10 D11 D12 D13 D14 D15 D16 D17 D18 D19 D20 D21 D22 D23 D24 D27 D29 D33 D34 E1 E2 E3 E4 E5 E6 E7 E8 E9 E10 E11 E12 E13 E14 E15 E16 E17 E18 E19 E20 E21 E22 E23 E24 E25 E27 E28 E30 E31 E33 E34 E36 E37 F2 F3 F4 F5 F6 F7 F8 F9 F10 F11 F12 F13 F14 F15 F16 F17 F18 F19 F20 F21 F22 F23 F24 F25 F26 F28 F29 F31 F32 F34 F35 F37 F38 G1 G2 G3 G4 G15 G16 G17 G18 G19 G20 G21 G22 G23 G24 G25 G28 G30 G31 G33 G34 G36 G37 H1 H3 H4 H5 H6 H7 H8 H9 H10 H11 H12 H13 H14 H15 H16 H17 H18 H19 H20 H21 H22 H23 H24 H25 H26 H28 H29 H32 H34 H35 H37 H38 J1 J2 J3 J4 J5 J6 J7 J8 J9 J10 J11 J12 J13 J14 J16 J17 J18 J19 J20 J21 J22 J23 J24 J25 J26 J27 J28 J30 J31 J33 J34 J36 J37 K1 K2 K3 K4 K5 K6 K7 K8 K9 K10 K11 K12 K13 K14 K15 K16 K17 K18 K19 K20 K21 K22 K23 K24 K25 K26 K27 K28 K29 K31 K32 K34 K35 K37 K38 L1 L2 L3 L4 L5 L6 L7 L8 L9 L10 L11 L12 L13 L14 L15 L16 L17 L18 L19 L20 L21 L22 L23 L24 L25 L26 L27 L28 L29 L32 L33 L36 L37 L40 M2 M3 M4 M5 M6 M7 M8 M9 M10 M11 M12 M13 M14 M15 M16 M17 M18 M19 M20 M21 M22 M23 M24 M25 M26 M27 M28 M30 M31 M34 M35 M38 M39 Y1 Y2 Y3 Y6 Y7 Y26 Y27 Y30 Y31 Y34 Y35 Y38 Y39 Z4 Z5 Z6 Z8 Z9 Z24 Z25 Z28 Z29 Z32 Z33 Z36 Z37 Z40; J31 4; NOREF#19 1; NOREF#20 1; NOREF#102 1; NOREF#149 1; NOREF#159 1; NOREF#161 1; NOREF#162 1; NOREF#167 1; NOREF#168 1; NOREF#174 1; NOREF#176 1; T2 2; U2 1 3 4; U3 5 28 32; U4 7 8 9 22 23 24 25 29 30 49 50 56 57 60 61; U5 7; U6 4; U8 21 22 23 24 30 32 33 34 36 45 46 60; U9 6 7; U13 1 3; U16 3 11 12 13; U21 2 4 5 6 9 17 18 19; U22 2 4 5 6 9 17 18 19

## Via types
v1: diameter 0.457, hole 0.203, TOP to BOTTOM, 1643 vias
v2: diameter 0.4, hole 0.203, TOP to BOTTOM, 51 vias
v3: diameter 0.508, hole 0.254, TOP to BOTTOM, 122 vias
v4: diameter 0.406, hole 0.203, TOP to BOTTOM, 88 vias
v5: diameter 0.559, hole 0.305, TOP to BOTTOM, 98 vias
v6: diameter 0.61, hole 0.33, TOP to BOTTOM, 16 vias
v7: diameter 0.762, hole 0.381, TOP to BOTTOM, 8 vias

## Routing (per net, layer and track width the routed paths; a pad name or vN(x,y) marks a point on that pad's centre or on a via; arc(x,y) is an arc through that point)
1.4V: length 2.8
  TOP w0.254: 54.36,4.19 v1(53.72,4.19)
  TOP w0.279: U17.4 53.6,4.31 v1(53.72,4.19) ; v1(53.73,3.09) 54.7,3.09 v1(54.74,3.05)
  BOTTOM w0.254: U20.5 64.22,5.8 v1(64.13,5.71)
  vias: v1(51.56,2.03) v1(54.94,11.3) v1(54.86,7.11) v1(54.99,12.57) v1(54.99,9.91) v1(55.75,7.75) v1(56.13,12.57) v1(56.13,9.65) v1(56.39,3.05) v1(56.52,6.48) v1(56.64,11.3) v1(57.53,7.24) v1(57.53,5.33) v1(57.79,12.57) v1(57.79,9.65) v1(58.29,2.92) v1(58.67,6.35) v1(58.67,4.45) v1(59.69,7.24) v1(59.82,3.05) v1(59.94,5.59) v1(60.45,4.06) v1(61.47,6.22) v1(61.47,4.7) v1(61.47,2.79) v1(61.72,7.47) v1(62.48,3.81) v1(62.61,5.84) v1(62.74,14.22) v1(62.87,7.75) v1(62.87,7.11) v1(63.37,6.35) v1(63.37,4.7) v1(63.37,2.79) v1(63.5,11.05) v1(64.9,4.32) v1(65.13,2.92)
5.0V_IN: length 24.6
  BOTTOM w0.127: v5(24.41,4.96) 24.42,4.95 v5(25.39,4.95) ; v5(24.41,4.96) 24.41,3.97 v5(24.39,3.95) ; v5(24.41,4.96) 24.39,4.98 v5(24.39,5.95) ; v5(24.41,4.96) 23.4,4.96 v5(23.39,4.95) ; v5(25.39,5.95) v5(25.39,6.95) v5(24.39,6.95) ; v5(25.39,5.95) v5(24.39,5.95) ; v5(25.39,5.95) v5(25.39,4.95) ; v5(24.39,5.95) v5(23.39,5.95) ; v5(24.39,5.95) v5(24.39,6.95) ; v5(23.39,3.95) v5(23.39,4.95) ; v5(23.39,3.95) v5(23.39,2.95) ; v5(23.39,3.95) v5(24.39,3.95) ; v5(23.39,4.95) v5(23.39,5.95) ; v5(23.39,5.95) v5(23.39,6.95) ; v5(23.39,6.95) 23.3,6.86 Q3.8 ; v5(23.39,6.95) v5(24.39,6.95) ; v5(25.39,3.95) v5(25.39,2.95) v5(24.39,2.95) ; v5(25.39,3.95) v5(25.39,4.95) ; v5(25.39,3.95) v5(24.39,3.95) ; Q3.5 23.3,3.05 v5(23.39,2.95) ; v5(23.39,2.95) v5(24.39,2.95) ; v5(24.39,2.95) v5(24.39,3.95)
  vias: v1(15.49,12.95) v1(15.49,2.03) v1(17.08,24.22) v1(17.2,33.62) v1(17.33,28.92) v1(18.16,11.43) v1(18.16,8.89) v1(18.67,1.9) v1(18.85,25.62) v1(19.3,12.19) v1(19.43,8.38) v1(20.76,31.71) v1(20.89,25.62) v1(20.89,24.09) v1(21.01,28.79) v1(21.21,1.78) v1(21.46,10.16) v1(22.35,14.48) v1(22.35,13.59) v1(22.66,31.71) v1(22.66,28.92) v1(22.86,9.91) v1(23.62,8.89) v1(24.44,33.62) v1(24.44,31.71) v1(24.57,24.09) v1(24.64,7.75) v1(25.27,16.51) v1(25.4,1.9)
5VIN: length 0.9
  TOP w0.254: v1(51.48,4.15) 51.64,4.31 U17.1 ; U17.7 51.8,5.66 v1(51.59,5.87)
  vias: v1(25.91,9.91) v1(26.67,8.89) v1(27.56,8.13) v1(27.66,6.86) v1(27.66,5.59) v1(27.66,4.32) v1(27.81,10.29) v1(27.81,9.14) v1(29.46,6.1) v1(29.46,4.72) v1(30.61,8.64) v1(30.99,9.4) v1(31.12,10.41) v1(31.37,7.75) v1(31.37,6.48) v1(32.13,7.11) v1(32.26,9.4) v1(32.64,10.41) v1(32.89,7.75) v1(32.89,6.48) v1(33.66,9.4) v1(33.91,7.11) v1(34.16,10.41) v1(34.42,8.64) v1(34.92,9.4) v1(34.92,5.33) v1(35.43,7.11) v1(35.56,8.38) v1(36.07,4.7) v1(36.83,7.11) v1(37.21,8.38) v1(37.34,4.85) v1(37.67,6.42) v1(37.67,5.66) v1(50.95,6.66) v1(51.09,5.33) v1(51.44,7.75) v1(51.62,6.66) v1(79.02,3.45) v1(80.01,2.29) v1(80.26,4.06) v1(80.52,3.05) v1(81.28,3.56) v1(81.28,1.78) v1(81.5,4.49) v1(81.79,2.54) v1(82.3,3.3) v1(82.55,1.78) v1(83.57,1.78) v1(92.08,10.79) v1(92.08,8.25) v1(93.34,9.52) v1(93.34,6.98) v1(94.61,10.79) v1(94.61,8.25) v1(95.91,3.45) v1(96.65,2.41) v1(96.77,3.94) v1(97.28,2.92) v1(97.54,1.65) v1(97.66,4.45) v1(98.04,3.68) v1(98.04,2.67) v1(98.55,1.78) v1(98.68,3.56) v1(99.19,2.92) v1(99.19,2.16) v1(99.82,1.52) v1(100.46,1.78) v5(59.31,9.02) v5(59.82,10.29)
+2.2V: length 22.9
  TOP w0.279: U14.4 39.02,3.75 v1(39.5,3.28) ; SJP3.3 60.71,11.3 58.17,13.84 50.42,13.84 48.39,11.81 46.61,11.81
  BOTTOM w0.305: v1(45.21,14.35) 45.26,14.31 U16.15 ; U16.17 44.5,16.06 v1(44.45,16)
  vias: v1(39.88,6.86) v1(40.64,13.34) v1(40.63,11.94) v1(40.77,10.67) v1(40.77,3.3) v1(40.89,8) v1(41.27,6.86) v1(41.4,13.34) v1(41.4,11.94) v1(41.4,10.54) v1(41.78,8.76) v1(42.16,3.3) v1(42.29,9.65) v1(42.55,13.72) v1(43.18,6.86) v1(43.31,12.19) v1(43.43,5.08) v1(43.69,3.3) v1(44.07,8.51) v1(44.2,14.48) v1(44.2,13.21) v1(44.7,9.65) v1(44.96,6.86) v1(45.09,5.08) v1(45.47,15.41) v1(45.47,3.56) v1(45.72,8.64) v1(46.33,11.05) v1(46.35,9.52) v1(46.48,12.45) v1(46.48,7.62) v1(47.62,9.65) v1(47.62,3.3) v1(49.15,6.98) v1(49.15,3.3)
+3.3V_LMX: length 14.9
  TOP w0.279: C106.1 62.94,112.87 v1(62.96,112.85)
  TOP w0.381: v1(66.13,116.19) 66.07,116.14 64.73,116.14 C100.1 ; v1(57.79,117.14) C101.1 C113.1 ; C106.1 62.13,113.38 C102.2 ; v1(62.59,122.57) v1(62.59,121.48) ; C103.1 v1(64.39,113.25)
  BOTTOM w0.279: U3.15 62.3,113.13 62.58,112.85 v1(62.96,112.85) ; v1(62.59,121.48) 62.8,121.27 U3.37
  BOTTOM w0.305: U3.26 v1(57.79,117.14) ; U3.21 58.66,114.64 58.4,114.37 v1(58.4,113.74) ; v1(64.39,113.25) 64.3,113.34 U3.11 ; v1(66.13,116.19) 66.07,116.14 U3.7
  vias: v1(57.41,118.71) v1(68.18,119.32) v1(86.11,14.1) v1(86.21,19.63) v1(86.36,18.69) v1(86.46,17.25) v1(86.61,15.54) v1(86.61,13.46) v1(87.12,19.81) v1(87.12,14.1) v1(87.25,18.29) v1(87.38,16.76) v1(87.38,14.86) v1(87.5,22.1) v1(88.39,18.16) v1(88.52,17.02) v1(89.15,22.48) v1(89.66,18.16) v1(90.93,22.35) v1(91.06,21.08) v1(91.06,19.56)
+3.3V_LMXRF: length 4.1
  TOP w0.381: v1(56.87,116.91) C99.1 v1(56.87,113.86)
  BOTTOM w0.254: R48.2 60.96,111.58 v1(60.53,111.58) 60.48,111.63 R49.2
  vias: v1(57.18,95.65) v1(57.84,93.58) v1(58.87,94.58) v1(59.87,95.8) v1(59.93,93.66) v1(61.13,94.59) v1(62.14,93.63) v1(62.24,95.66) v1(80.39,19.3) v1(80.92,20.19) v1(80.9,18.41) v1(81.03,21.34) v1(81.53,19.43) v1(82.68,17.91) v1(83.57,18.54) v1(85.34,21.34)
+3.3VCLK: length 3.8
  TOP w0.279: v1(94.21,108.4) 93.83,108.02 FB10.1
  TOP w0.508: v1(98.27,95.19) 98.15,95.07 96.75,95.07 FB5.1 ; FB2.1 v1(90.91,97.86)
  vias: v1(77.75,104.08) v1(78.34,104.08) v1(78.93,104.08) v1(79.55,104.2) v1(80.75,122.88) v1(86.97,105) v1(86.97,103.12) v1(88.75,111.9) v1(88.76,111.26) v1(88.82,110.63) v1(89.38,111.6) v1(89.36,110.8) v1(89.77,97.81) v1(90.32,97.83) v1(90.52,97.3) v1(99.8,95.19) v1(102.08,95.32) v1(103.1,108.53) v1(103.5,20.98) v1(103.61,19.53) v1(103.76,17.83) v1(103.73,16.05) v1(104.39,21.59) v1(104.39,20.32) v1(104.52,17.02) v1(105.16,15.87) v1(105.28,20.7) v1(105.92,21.59) v1(105.92,16.38) v1(107.06,20.57) v1(107.67,101.92)
GND: length 122.4
  TOP w0.127: v1(31.33,73.68) 30.54,74.46 v1(30.54,74.48) ; v1(30.53,72.08) v1(31.33,72.88)
  TOP w0.254: v1(37.73,75.28) v1(36.92,75.28) ; U8.13 v1(53.43,36.86) ; U8.10 53.76,38.37 v1(53.67,38.28) 53.67,38.11 53.77,38.02 ; v5(99.77,4.77) 100.08,4.47 C235.2 ; C157.2 101.58,99 v3(101.07,99.51) ; U8.35 64.68,36.36 v1(64.69,36.37) ; v1(30.52,68.88) 30.5,68.88 29.82,68.2 v1(29.82,68.12) ; v1(31.33,69.68) U1.M2 ; U2.9 v1(30.9,109.2) ; v1(29.34,77.72) 29.38,77.68 v1(30.52,77.68) ; v1(35.33,69.68) v1(35.33,68.88) ; R173.1 101.83,5.82 v5(101.8,5.79) ; v1(30.66,108.42) 30.38,108.7 U2.8 ; U12.10 86.47,45.87 v1(86.25,46.1) ; 59.31,33.53 59.31,33.42 v1(59.05,33.17) ; v1(32.12,77.68) v1(32.12,76.88) ; v1(33.73,69.68) U1.L6 v1(34.52,68.88) ; v1(34.52,77.68) U1.B6 ; v1(32.12,69.68) v1(32.12,68.88) ; v1(35.33,77.68) v1(35.33,76.88) ; U11.10 v1(82.06,36.13) ; v1(54.48,43.17) 54.48,43.55 v1(54.69,43.76) ; U12.7 82.84,45.87 v1(83.07,46.1) ; U1.A2 v1(31.33,76.88) ; U12.2 v1(83.04,49.12) ; v1(61.81,44.57) U8.51 ; U12.1 v1(80.8,49.77) ; v1(37.73,73.68) v1(36.92,73.68) ; U8.15 53.64,35.86 v1(53.59,35.81) ; R170.1 101.09,4.47 v5(100.79,4.77) ; R171.1 102.11,4.47 v5(101.8,4.77) ; v1(53.57,5.87) 53.49,5.78 arc(53.34,5.69) U17.5 ; U12.8 v1(81.95,44.47)
  TOP w0.279: R99.2 v1(105.77,103.41) ; C114.1 56.19,118.71 v1(55.55,118.07) ; U8.11 53.92,37.87 53.77,38.02 ; v1(35.33,68.88) 34.99,68.54 34.99,68.2
  TOP w0.305: C106.2 63.31,112.26 v1(63.32,112.27) ; U8.47 v1(64.72,42.37) ; v1(56.11,118) 56.16,117.95 C109.2 ; U8.5 v1(53.24,40.87) ; U8.1 v1(54.48,43.17) ; 59.31,33.53 U8.25
  TOP w0.356: U10.7 v1(47.22,25.68) ; U10.10 v1(55.85,25.68)
  TOP w0.381: C100.2 63.83,116.12 v6(63.58,116.38) ; C107.1 63.05,123.18 v1(63.35,122.88) ; v3(101.07,105.61) 101.58,106.12 C166.2 ; C99.2 55.98,115.11 v1(55.98,114.03) ; v3(94.97,100.53) 94.46,100.02 C156.1 ; v3(95.99,105.61) 96.24,105.86 C165.2 ; C158.2 99.8,99.26 v3(100.05,99.51) ; C101.2 60.36,117.39 v6(60.53,117.39) ; C113.2 60.53,118.36 v6(60.53,118.41) ; C102.1 62.33,115.13 v6(62.56,115.36) ; v3(97,99.51) 97.26,99.26 C159.2 ; C163.2 101.2,100.4 v3(101.07,100.53) ; v6(63.58,115.36) 64.19,114.75 C104.1 ; v1(65.55,113.59) 65.32,113.81 C103.2 ; C155.1 94.46,99 v3(94.97,99.51) ; v3(101.07,101.54) 101.32,101.8 C154.1 ; U14.5 38.87,6.42 38.87,6.42 38.87,8.01 v1(39.24,8.38)
  TOP w0.508: C164.2 v1(106.17,101.23) ; v1(101.22,36.58) 101.47,36.32 U15.4 ; R106.2 v1(130.84,90.02)
  L10_SIG-2 w0.635: v1(148.08,96.39) 148.97,95.5 v1(148.97,87) v1(148.97,84.45)
  L11_GND-6 w0.203: 123.87,79.5 123.88,79.5 123.9,79.5 ; 123.87,80.21 123.88,80.21 123.9,80.21
  BOTTOM w0.152: v6(63.58,115.36) 63.3,115.09 U3.13 63.3,113.13 63.42,113.01 63.42,112.46 63.32,112.37 v1(63.32,112.27)
  BOTTOM w0.254: v1(34.52,73.68) 34.48,73.63 C64.2 ; v1(89.77,103.12) 89.95,102.94 R188.2 R189.2 ; v1(36.92,71.28) 36.93,71.27 C96.2 ; v1(36.92,73.68) 36.92,73.86 C89.2 ; v6(63.58,117.39) 63.82,117.64 U3.4 ; C88.2 37.73,73.84 v1(37.73,73.68) ; C55.2 33.76,76.85 v1(33.73,76.88) ; C61.2 32.21,76.96 v1(32.12,76.88) ; v1(32.93,76.88) 32.94,76.86 C69.2 ; U21.7 v1(104.1,6.44) ; C56.2 34.51,75.26 v1(34.52,75.28) ; v1(31.33,72.88) 31.32,72.87 C73.2 ; v1(31.33,73.68) 31.34,73.7 C70.2 ; v6(62.56,115.36) 62.8,115.12 U3.14 ; U3.34 61.3,118.65 v6(61.55,118.41) ; v1(37.73,71.28) 37.74,71.26 C85.2 ; v1(61.81,44.57) 61.81,44.61 61.42,44.99 61.42,45.08 C176.2 ; C63.2 34.49,72.85 v1(34.52,72.88) ; C57.2 30.56,71.25 v1(30.52,71.28) ; v1(90.15,100.53) 90.16,100.54 C137.1 ; v1(32.12,73.68) 32.13,73.69 C71.2 ; U3.6 63.84,116.64 v6(63.58,116.38) ; v1(33.73,69.68) 33.73,69.69 C59.2 ; C24.1 v1(88.88,102.05) ; R63.2 93.65,94.25 v1(93.47,94.43) ; C86.2 37.74,72.86 v1(37.73,72.88) ; v1(35.12,82.19) 34.94,82.01 34.58,82.01 34.54,82.04 C67.2 ; v1(54.48,43.17) 54.69,43.38 C181.2 ; C54.2 30.54,75.26 v1(30.52,75.28) ; C90.2 37.72,75.29 v1(37.73,75.28) ; v1(36.92,75.28) 36.93,75.29 C91.2 ; v1(34.52,72.08) 34.48,72.03 C62.2 ; v6(60.53,116.38) 60.27,116.64 U3.25 ; v1(53.67,38.28) 54.21,37.74 54.48,37.74 C182.2 ; v6(63.58,118.41) 63.8,118.64 ; 63.8,118.64 U3.39 ; 63.8,118.64 U3.2 ; R52.1 v1(62.03,108.33) ; C74.2 32.92,69.69 v1(32.93,69.68) ; C65.2 34.49,74.45 v1(34.52,74.48) ; C72.2 32.13,72.87 v1(32.12,72.88) ; C188.2 62.48,35.48 ; v1(53.59,35.81) 53.43,35.98 v1(53.43,36.86) ; v1(52.45,41.4) 52.65,41.61 C169.2 ; C87.2 36.93,72.87 v1(36.92,72.88) ; R53.1 v1(58.98,108.1)
  BOTTOM w0.279: v1(35.12,79.82) 34.99,79.69 34.71,79.69 34.57,79.55 C60.2 33.27,80.01 C66.2 ; U3.31 v1(59.08,119.91) ; C58.2 v1(28.07,75.18) ; C187.2 61.87,39.88 61.86,39.87 ; 63.74,36.54 63.75,36.55 C183.2 ; v6(62.56,117.39) U3.41 ; U3.40 v1(64.3,120.91)
  BOTTOM w0.305: U22.7 v1(87.72,6.44) ; v1(32,14.1) C175.2 ; U16.8 v1(51.12,16.71) ; v3(44.04,17.14) 44.48,16.71 U16.18 ; C195.2 v1(89.19,49.25)
  BOTTOM w0.356: U20.17 v1(69.3,9.06) ; U20.2 v1(66.74,5.14) ; U20.4 v1(65.44,5.12) ; U20.14 v1(66.74,11.75) ; U20.13 v1(66.09,11.76) ; U20.12 v1(65.44,11.78) ; U20.3 v1(66.09,5.13)
  BOTTOM w0.508: v1(29.84,14.2) 29.95,14.1 C175.2 ; v1(78.97,50.71) 78.52,50.27 C180.2
  vias: v1(0.2,87.27) v1(0.2,84.72) v1(0.26,74.55) v1(0.21,72.02) v1(0.22,61.84) v1(0.21,59.3) v1(0.2,49.15) v1(0.2,46.62) v1(0.2,36.45) v1(0.2,33.92) v1(0.51,90.42) v1(0.51,81.53) v1(0.51,77.72) v1(0.51,68.83) v1(0.51,65.02) v1(0.51,56.13) v1(0.51,52.32) v1(0.51,43.43) v1(0.51,39.62) v1(0.51,30.73) v1(0.89,111.76) v1(0.89,109.22) v1(0.89,106.05) v1(0.89,103.5) v1(0.89,100.58) v1(0.89,98.04) v1(0.89,95.76) v1(0.89,93.22) v1(1.27,22.1) v1(1.27,19.56) v1(1.27,0.89) v1(1.52,90.42) v1(1.52,81.53) v1(1.52,77.72) v1(1.52,68.83) v1(1.52,65.02) v1(1.52,56.13) v1(1.52,52.32) v1(1.52,43.43) v1(1.52,39.62) v1(1.52,30.73) v1(1.66,26.42) v1(1.66,25.15) v1(1.66,17.52) v1(1.66,16.25) v1(2.08,84.72) v1(2.18,87.24) v1(2.54,90.42) v1(2.54,81.53) v1(2.54,77.72) v1(2.54,68.83) v1(2.54,65.02) v1(2.54,56.13) v1(2.54,52.32) v1(2.54,43.43) v1(2.54,39.62) v1(2.54,30.73) v1(2.55,25.79) v1(2.55,16.89) v1(2.76,72.02) v1(2.84,74.55) v1(2.78,61.84) v1(2.76,59.31) v1(3.2,49.12) v1(3.2,46.59) v1(3.2,36.42) v1(3.2,33.89) v1(3.43,119.34) v1(3.43,112.14) v1(3.44,26.42) v1(3.44,25.15) v1(3.44,17.52) v1(3.44,16.25) v1(3.56,90.42) v1(3.56,81.53) v1(3.56,77.72) v1(3.56,68.83) v1(3.56,65.02) v1(3.56,56.13) v1(3.56,52.32) v1(3.56,43.43) v1(3.56,39.62) v1(3.56,30.73) v1(3.81,0.89) v1(4.52,84.72) v1(4.57,90.42) v1(4.57,81.53) v1(4.57,77.72) v1(4.57,68.83) v1(4.57,65.02) v1(4.57,56.13) v1(4.57,52.32) v1(4.57,43.43) v1(4.57,39.62) v1(4.57,30.73) v1(4.74,87.25) v1(4.93,72.02) v1(5.01,74.56) v1(5.46,77.52) v1(5.97,119.34) v1(5.97,112.14) v1(6.11,87.24) v1(6.11,84.71) v1(6.11,61.84) v1(6.11,59.31) v1(6.64,74.54) v1(6.58,72.03) v1(6.94,49.14) v1(6.94,46.61) v1(6.94,36.44) v1(6.93,33.91) v1(7.12,26.42) v1(7.12,25.15) v1(7.12,17.52) v1(7.12,16.25) v1(7.24,19.68) v1(7.49,0.89) v1(8.05,25.79) v1(8.05,16.89) v1(8.15,19.74) v1(8.55,74.54) v1(8.65,87.24) v1(8.65,84.71) v1(8.65,61.84) v1(8.65,59.31) v1(8.88,72.02) v1(9.03,26.42) v1(9.03,25.15) v1(9.02,19.68) v1(9.03,17.52) v1(9.03,16.25) v1(9.65,119.34) v1(9.65,112.14) v1(10.01,49.17) v1(10.03,46.6) v1(10.04,44.36) v1(10.04,41.56) v1(10.03,39.25) v1(10,36.47) v1(10,33.94) v1(10.03,0.89) v1(10.24,75.35) v1(11.01,72.76) v1(11.19,87.24) v1(11.19,84.71) v1(11.19,61.84) v1(11.19,59.31) v1(11.96,48.28) v1(12.13,75.81) v1(12.19,119.34) v1(12.19,112.14) v1(12.27,35.34) v1(12.47,73.29) v1(12.56,46.29) v1(12.57,44.01) v1(12.58,39.07) v1(12.58,37.5) v1(12.93,93.6) v1(12.94,91.07) v1(12.94,80.89) v1(12.94,78.37) v1(12.93,68.2) v1(12.93,65.67) v1(12.94,55.49) v1(12.94,52.96) v1(13.21,0.89) v1(13.73,87.24) v1(13.73,84.71) v1(13.73,61.84) v1(13.73,59.31) v1(14.03,75.81) v1(14.07,93.59) v1(14.12,91.08) v1(14.07,80.89) v1(14.12,78.37) v1(14.12,73.29) v1(14.27,72.01) v1(14.47,68.2) v1(14.47,65.68) v1(14.53,55.49) v1(14.53,52.97) v1(15.16,119.34) v1(15.37,112.14) v1(15.75,0.89) v1(15.85,61.85) v1(15.85,59.32) v1(15.97,75.81) v1(16.1,87.26) v1(16.09,84.72) v1(16.21,93.59) v1(16.21,91.07) v1(16.21,80.89) v1(16.21,78.37) v1(16.21,68.19) v1(16.21,65.67) v1(16.21,55.49) v1(16.21,52.97) v1(17.28,74.54) v1(17.28,73.27) v1(17.28,72) v1(17.7,119.34) v1(17.91,112.14) v1(18.47,75.75) v1(18.75,93.59) v1(18.75,91.07) v1(18.75,80.89) v1(18.75,78.37) v1(18.75,68.19) v1(18.75,65.67) v1(18.75,55.49) v1(18.75,52.97) v1(18.8,0.89) v1(20.95,112.14) v1(21.01,119.34) v1(21.25,71.48) v1(21.29,93.59) v1(21.29,91.07) v1(21.29,80.89) v1(21.29,78.37) v1(21.29,68.19) v1(21.29,65.67) v1(21.29,55.49) v1(21.29,52.97) v1(21.34,0.89) v1(21.5,75.12) v1(23.37,12.32) v1(23.37,11.56) v1(23.55,119.34) v1(23.5,112.14) v1(23.83,93.59) v1(23.83,91.07) v1(23.83,80.89) v1(23.83,78.37) v1(23.83,68.19) v1(23.83,65.67) v1(23.83,55.49) v1(23.83,52.97) v1(24.26,74.98) v1(24.89,0.89) v1(25.32,111.22) v1(25.45,112.36) v1(25.93,52.98) v1(26.06,68.18) v1(26.05,60.32) v1(26.11,91) v1(26.07,85.73) v1(26.12,81.01) v1(26.23,71.58) v1(26.22,65.5) v1(26.17,55.61) v1(26.28,88.79) v1(26.32,83.2) v1(26.31,64.22) v1(26.32,57.79) v1(26.31,56.79) v1(26.42,78.41) v1(26.5,60.85) v1(26.73,86.25) v1(26.7,63) v1(26.85,119.34) v1(26.84,93.4) v1(26.77,75) v1(27.07,60.31) v1(27.36,111.47) v1(27.36,109.06) v1(27.43,14.73) v1(27.43,13.97) v1(27.43,0.89) v1(27.53,85.72) v1(27.64,60.84) v1(27.7,53.57) v1(27.94,14.35) v1(27.99,67.31) v1(28.14,86.24) v1(28.11,60.32) v1(28.28,92.4) v1(28.37,109.06) v1(28.36,79.6) v1(28.45,14.73) v1(28.45,13.97) v1(28.65,78.36) v1(28.74,71.86) v1(28.71,54.93) v1(28.83,90.8) v1(28.86,88.8) v1(28.76,65.84) v1(28.85,64.53) v1(28.85,63.32) v1(28.86,57.79) v1(28.84,56.47) v1(28.86,82.24) v1(28.86,81.14) v1(28.96,10.29) v1(29,83.29) v1(29.39,119.34) v1(29.39,109.06) v1(29.45,65.24) v1(29.48,63.74) v1(29.46,3.15) v1(29.59,75.54) v1(29.82,67.31) v1(29.84,9.52) v1(29.92,66.67) v1(29.99,57.8) v1(30.22,65.2) v1(30.45,88.76) v1(30.4,79.38) v1(30.4,78.59) v1(30.48,86.25) v1(30.52,64) v1(30.5,60.32) v1(30.73,0.89) v1(30.8,31.62) v1(30.8,26.54) v1(31.22,57.79) v1(31.34,86.24) v1(31.33,60.32) v1(31.37,4.7) v1(31.37,3.56) v1(31.53,64.78) v1(31.53,63.91) v1(32.07,31.62) v1(32.07,26.54) v1(32.13,4.06) v1(32.38,88.55) v1(32.69,119.34) v1(32.69,58.18) v1(32.77,4.7) v1(32.77,3.43) v1(32.92,15.75) v1(33.34,31.62) v1(33.34,26.54) v1(33.27,0.89) v1(33.63,87.52) v1(33.77,98.45) v1(33.81,59.2) v1(34.51,76.89) v1(34.51,76.09) v1(34.52,71.28) v1(34.68,60.13) v1(34.82,86.2) v1(35.11,84.31) v1(35.12,67.87) v1(35.12,65.24) v1(35.13,62.79) v1(35.07,61.03) v1(35.23,119.34) v1(36.58,0.89) v1(36.83,15.87) v1(37.03,43.89) v1(37.2,98.45) v1(37.34,15.24) v1(37.57,17.27) v1(37.92,43.26) v1(38.1,19.94) v1(38.1,18.8) v1(38.81,42.5) v1(38.86,100.03) v1(39.33,77.68) v1(39.33,76.88) v1(39.33,69.68) v1(39.33,68.88) v1(39.5,2.13) v1(39.72,99.09) v1(40.48,99.98) v1(40.48,98.21) v1(40.89,5.59) v1(41.33,77.34) v1(41.33,69.34) v1(41.58,68.2) v1(41.63,67.18) v1(41.78,5.21) v1(42.42,0.89) v1(44.17,124.4) v1(44.32,11.18) v1(44.96,23.24) v1(44.96,0.89) v1(46.71,124.4) v1(47.09,29.34) v1(47.5,12.45) v1(47.9,11.05) v1(48.13,0.89) v1(48.92,22.23) v1(48.9,8.64) v1(49.4,9.52) v1(50.01,124.4) v1(50.29,0.89) v1(50.8,45.59) v1(50.8,39.5) v1(52.55,124.4) v1(52.62,121.99) v1(52.62,119.2) v1(52.62,116.4) v1(52.62,113.61) v1(52.65,38.86) v1(52.94,114.5) v1(52.96,19.56) v1(52.98,18.43) v1(52.98,17.26) v1(52.98,16.12) v1(52.98,14.98) v1(53.49,50.52) v1(53.47,7.75) v1(53.72,1.9) v1(54.03,120.21) v1(55.43,121.97) v1(55.6,124.4) v1(55.75,4.7) v1(55.96,120.06) v1(55.91,28.96) v1(57.38,102.31) v1(58.14,124.4) v1(59.11,113.99) v1(59.57,120.31) v1(59.62,105.81) v1(59.72,98.75) v1(60.53,110.97) v1(60.81,123.01) v1(61.09,1.02) v1(61.44,124.4) v1(61.44,122.32) v1(61.47,105.79) v1(61.55,98.72) v1(62,122.75) v1(63.63,1.02) v1(63.86,121.53) v1(63.98,124.4) v1(64.18,29.4) v1(64.38,43.69) v1(64.72,122.57) v1(64.7,121.3) v1(64.7,119.73) v1(65.15,43.56) v1(65.56,122.72) v1(65.56,121.3) v1(65.63,31.3) v1(65.79,46.1) v1(65.91,4.32) v1(66.17,45.59) v1(66.55,46.1) v1(66.7,2.92) v1(66.67,1.02) v1(66.91,98.11) v1(67.03,124.4) v1(67.41,116.38) v1(68.53,122.57) v1(68.99,12.45) v1(69.14,101.62) v1(69.24,94.56) v1(69.22,1.02) v1(69.34,17.65) v1(69.34,4.32) v1(69.37,122.75) v1(69.47,21.49) v1(69.57,124.4) v1(70.48,2.16) v1(70.61,11.58) v1(71,101.59) v1(71.07,94.53) v1(71.12,21.34) v1(71.37,1.02) v1(72.87,124.4) v1(73.53,3.66) v1(73.79,20.57) v1(73.91,1.02) v1(75.03,97.23) v1(75.3,36.74) v1(75.41,124.4) v1(75.44,20.09) v1(76.05,106.5) v1(76.05,105.35) v1(76.04,39.66) v1(76.38,122.5) v1(76.51,107.51) v1(76.83,19.3) v1(77.09,1.02) v1(78.34,97.23) v1(79.02,5.03) v1(79.1,106.5) v1(79.35,20.19) v1(79.58,21.34) v1(79.63,1.02) v1(79.73,123.9) v1(79.89,107.26) v1(79.91,105.56) v1(80,38.01) v1(80.42,104.26) v1(80.75,13.03) v1(80.95,103.27) v1(80.88,101.57) v1(81.59,105.56) v1(81.65,38.01) v1(81.58,11.33) v1(81.58,10.21) v1(81.92,107.26) v1(81.96,100.78) v1(82.15,121.36) v1(82.15,118.82) v1(82.15,116.28) v1(82.35,103.25) v1(82.43,104.87) v1(83.54,105.02) v1(83.54,103.14) v1(83.47,101.54) v1(84.58,15.54) v1(84.85,39.41) v1(84.89,17.25) v1(85.13,99.51) v1(85.1,49.78) v1(85.34,18.69) v1(85.6,19.63) v1(86.11,1.02) v1(86.61,3.45) v1(86.72,124.4) v1(87.35,100.93) v1(87.73,105) v1(87.73,103.12) v1(88.37,100.71) v1(88.5,98.57) v1(88.62,107.18) v1(88.65,1.02) v1(89.19,50.67) v1(89.33,107.26) v1(89.51,124.4) v1(89.53,40.04) v1(89.53,38.9) v1(89.53,37.76) v1(89.53,36.61) v1(89.64,109.42) v1(89.64,108.27) v1(89.77,105) v1(91.04,107.13) v1(91.44,100.32) v1(91.57,114.68) v1(91.57,112.36) v1(91.82,1.02) v1(92.05,124.4) v1(92.83,111.91) v1(92.88,109.8) v1(93.22,114.75) v1(93.22,112.44) v1(93.86,109.27) v1(94.1,111.77) v1(94.1,109.89) v1(94.35,51.02) v1(94.61,1.02) v1(95.35,124.4) v1(95.51,95.7) v1(95.91,5.03) v1(96.14,108.78) v1(96.14,21.59) v1(96.24,20.19) v1(97.49,95.7) v1(97.64,13.03) v1(97.89,124.4) v1(97.87,108.78) v1(98.53,96.64) v1(98.48,11.33) v1(98.48,10.21) v1(100.11,111.35) v1(100.08,36.58) v1(100.43,124.4) v1(100.74,114.73) v1(101.73,45.72) v1(101.73,17.83) v1(101.78,109.65) v1(101.99,111.35) v1(102.03,19.53) v1(102.39,114.8) v1(102.47,112.77) v1(102.49,20.98) v1(102.49,1.02) v1(102.72,107.44) v1(102.74,21.92) v1(102.95,111.88) v1(102.97,124.4) v1(103.5,3.45) v1(103.63,106.93) v1(103.74,109.62) v1(103.72,95.27) v1(104.14,108.35) v1(105.01,107.64) v1(105.03,1.02) v1(105.34,105.61) v1(105.39,124.4) v1(105.39,121.86) v1(105.39,119.07) v1(105.39,116.53) v1(105.46,112.34) v1(105.59,95.27) v1(106.26,97.43) v1(106.26,95.4) v1(106.4,107.72) v1(106.4,105.84) v1(106.4,105.23) v1(106.4,103.35) v1(106.4,43.69) v1(106.4,42.04) v1(108.13,97.43) v1(108.13,95.4) v1(108.61,105.46) v1(108.84,1.02) v1(108.89,107.61) v1(109.73,35.31) v1(109.98,45.85) v1(110.87,35.31) v1(111.25,15.11) v1(111.25,12.57) v1(111.38,39.75) v1(111.38,8.51) v1(111.38,5.97) v1(111.38,1.02) v1(112.52,39.75) v1(117.22,43.9) v1(117.73,96.9) v1(118.49,43.9) v1(119.25,94.21) v1(119.25,29.97) v1(120.27,96.9) v1(121.79,29.97) v1(122.73,37.46) v1(123.57,96.9) v1(124.21,29.97) v1(126.11,96.9) v1(126.75,29.97) v1(127.89,96.52) v1(128.91,88.39) v1(128.91,52.83) v1(128.91,49.02) v1(128.91,47.75) v1(128.91,43.94) v1(128.91,42.67) v1(128.91,38.86) v1(129.03,29.97) v1(130.18,51.56) v1(130.18,50.29) v1(130.18,46.48) v1(130.18,45.21) v1(130.18,41.4) v1(130.18,40.13) v1(130.43,96.52) v1(131.44,51.56) v1(131.44,47.75) v1(131.44,43.94) v1(131.44,40.13) v1(131.57,29.97) v1(132.72,52.83) v1(132.72,49.02) v1(132.72,45.21) v1(132.72,41.4) v1(132.72,38.86) v1(133.99,55.37) v1(133.99,51.56) v1(133.99,47.75) v1(133.99,43.94) v1(133.99,40.13) v1(135.25,83.31) v1(135.25,79.5) v1(135.25,75.69) v1(135.25,71.88) v1(135.25,56.64) v1(135.25,52.83) v1(135.25,49.02) v1(135.25,45.21) v1(135.25,41.4) v1(135.25,38.86) v1(136.52,55.37) v1(136.52,51.56) v1(136.52,47.75) v1(136.52,43.94) v1(136.52,40.13) v1(137.29,29.97) v1(137.8,56.64) v1(137.8,52.83) v1(137.8,49.02) v1(137.8,45.21) v1(137.8,41.4) v1(137.8,38.86) v1(138.94,96.27) v1(139.06,57.91) v1(139.06,54.1) v1(139.06,42.67) v1(139.06,40.13) v1(139.83,29.97) v1(140.33,83.31) v1(140.33,79.5) v1(140.33,59.18) v1(140.33,57.91) v1(140.33,54.1) v1(140.33,52.83) v1(140.33,49.02) v1(140.33,47.75) v1(140.33,43.94) v1(140.33,41.4) v1(140.33,38.86) v1(141.48,96.27) v1(141.61,85.85) v1(141.61,82.04) v1(141.61,80.77) v1(141.61,76.96) v1(141.61,75.69) v1(141.61,71.88) v1(141.61,70.61) v1(141.61,66.8) v1(141.61,56.64) v1(141.61,55.37) v1(141.61,51.56) v1(141.61,50.29) v1(141.61,46.48) v1(141.61,45.21) v1(141.61,41.4) v1(141.61,40.13) v1(142.75,29.97) v1(142.88,88.39) v1(142.88,84.58) v1(142.88,83.31) v1(142.88,78.23) v1(142.88,74.42) v1(142.88,73.15) v1(142.88,69.34) v1(142.88,68.07) v1(142.88,64.26) v1(142.88,59.18) v1(142.88,57.91) v1(142.88,54.1) v1(142.88,52.83) v1(142.88,49.02) v1(142.88,47.75) v1(142.88,43.94) v1(142.88,42.67) v1(142.88,38.86) v1(144.14,87.12) v1(144.14,85.85) v1(144.14,80.77) v1(144.14,76.96) v1(144.14,75.69) v1(144.14,61.72) v1(144.14,60.45) v1(144.14,56.64) v1(144.14,55.37) v1(144.14,51.56) v1(144.14,50.29) v1(144.14,46.48) v1(144.14,45.21) v1(144.14,41.4) v1(144.14,40.13) v1(145.29,29.97) v1(145.42,84.58) v1(145.42,83.31) v1(145.42,79.5) v1(145.42,78.23) v1(145.42,74.42) v1(145.42,73.15) v1(145.42,59.18) v1(145.42,57.91) v1(145.42,54.1) v1(145.42,52.83) v1(145.42,49.02) v1(145.42,47.75) v1(145.42,43.94) v1(145.42,42.67) v1(145.42,38.86) v1(145.54,96.39) v1(148.97,75.06) v1(148.97,72.52) v1(148.97,62.48) v1(148.97,59.94) v1(148.97,50.16) v1(148.97,47.62) v1(148.97,39.24) v1(148.97,36.7) v1(149.1,92.71) v1(149.1,90.17) v1(149.1,80.77) v1(149.1,78.23) v1(149.1,68.2) v1(149.1,65.66) v1(149.1,55.88) v1(149.1,53.34) v1(149.1,44.96) v1(149.1,42.42) v1(149.23,32.51) v1(149.23,29.97) v2(35.66,90.73) v2(36.49,90.73) v2(139.06,85.85) v2(139.06,82.04) v2(142.88,79.5) v2(144.14,71.88) v2(144.14,70.61) v2(144.14,66.8) v2(144.14,65.53) v2(145.42,69.34) v2(145.42,68.07) v2(145.42,64.26) v2(145.42,62.99) v3(17.4,87.22) v3(17.4,84.73) v3(17.4,61.82) v3(17.4,59.33) v3(18.06,86.77) v3(18.06,85.19) v3(18.06,61.37) v3(18.06,59.79) v3(18.31,85.98) v3(18.31,60.58) v3(18.92,87.22) v3(18.92,86.77) v3(18.92,85.19) v3(18.92,84.73) v3(18.92,61.82) v3(18.92,61.37) v3(18.92,59.79) v3(18.92,59.33) v3(23.27,86.72) v3(23.27,85.24) v3(23.27,61.32) v3(23.27,59.84) v3(24.1,87.5) v3(24.1,84.45) v3(24.1,62.1) v3(24.1,59.05) v3(24.36,88.29) v3(24.36,86.72) v3(24.36,85.24) v3(24.36,83.67) v3(24.36,62.89) v3(24.36,61.32) v3(24.36,59.84) v3(24.36,58.27) v3(25.02,88.75) v3(25.02,86.26) v3(25.02,85.7) v3(25.02,83.21) v3(25.02,63.35) v3(25.02,60.86) v3(25.02,60.3) v3(25.02,57.81) v3(41.91,17.53) v3(41.91,16.76) v3(43.18,17.53) v3(43.18,16.76) v3(43.69,22.1) v3(43.69,20.7) v3(44.07,22.96) v3(44.07,21.46) v3(44.07,19.96) v3(71.04,16.03) v3(74.8,15.24) v3(94.97,105.61) v3(94.97,104.59) v3(94.97,103.58) v3(94.97,102.56) v3(94.97,101.54) v3(95.99,104.59) v3(95.99,103.58) v3(95.99,102.56) v3(95.99,101.54) v3(95.99,100.53) v3(95.99,99.51) v3(97,105.61) v3(97,104.59) v3(97,103.58) v3(97,102.56) v3(97,101.54) v3(97,100.53) v3(98.02,105.61) v3(98.02,104.59) v3(98.02,103.58) v3(98.02,102.56) v3(98.02,101.54) v3(98.02,100.53) v3(98.02,99.51) v3(99.04,105.61) v3(99.04,104.59) v3(99.04,103.58) v3(99.04,102.56) v3(99.04,101.54) v3(99.04,100.53) v3(99.04,99.51) v3(100.05,105.61) v3(100.05,104.59) v3(100.05,103.58) v3(100.05,102.56) v3(100.05,101.54) v3(100.05,100.53) v3(101.07,104.59) v3(101.07,103.58) v3(101.07,102.56) v4(18.66,76.93) v4(21.05,76.93) v4(23.22,74.55) v4(23.22,72.01) v4(25.42,71.25) v4(25.42,68.86) v4(38.23,90.98) v4(38.23,88.6) v4(41.18,93.6) v4(41.18,91.21) v4(69.03,112.08) v4(70.72,113.77) v4(95.3,92.46) v4(95.81,112.23) v4(97.69,92.46) v4(98.2,112.23) v4(106,93.76) v4(106.68,87.43) v4(106.68,85.04) v4(106.81,71.28) v4(108.39,93.76) v4(108.5,72.97) v4(108.88,90.55) v4(108.88,88.16) v4(108.88,54.03) v4(108.88,51.65) v4(110.25,61.46) v4(110.87,82.25) v4(110.87,79.87) v4(111.92,68.67) v4(111.94,59.77) v4(113.61,66.99) v4(115.71,59.7) v4(115.71,57.31) v4(116.96,67.04) v4(116.96,64.65) v4(117.45,79.58) v4(117.41,56.59) v4(117.41,54.21) v4(119.14,77.89) v4(119.17,63.87) v4(119.17,61.48) v4(121.65,72.94) v4(121.65,70.55) v4(121.92,78.7) v4(121.92,76.31) v4(124.12,75.3) v4(124.12,72.91) v5(46.86,17.72) v5(46.86,16.71) v5(46.86,15.69) v5(47.87,17.72) v5(47.87,16.71) v5(47.87,15.69) v5(48.89,17.72) v5(48.89,16.71) v5(48.89,15.69) v5(57.53,40.64) v5(57.53,39.62) v5(57.53,38.61) v5(57.53,37.59) v5(58.04,40.13) v5(58.04,39.12) v5(58.04,38.1) v5(58.55,40.64) v5(58.55,39.62) v5(58.55,38.61) v5(58.55,37.59) v5(59.05,40.13) v5(59.05,39.12) v5(59.05,38.1) v5(59.56,40.64) v5(59.56,39.62) v5(59.56,38.61) v5(59.56,37.59) v5(60.07,40.13) v5(60.07,39.12) v5(60.07,38.1) v5(60.58,40.64) v5(60.58,39.62) v5(60.58,38.61) v5(60.58,37.59) v5(64.69,9.81) v5(64.69,9.11) v5(64.69,8.41) v5(64.69,7.71) v5(64.69,7.01) v5(65.39,9.81) v5(65.39,9.11) v5(65.39,8.41) v5(65.39,7.71) v5(65.39,7.01) v5(66.09,9.81) v5(66.09,9.11) v5(66.09,8.41) v5(66.09,7.71) v5(66.09,7.01) v5(66.79,9.81) v5(66.79,9.11) v5(66.79,8.41) v5(66.79,7.71) v5(66.79,7.01) v5(67.49,9.81) v5(67.49,9.11) v5(67.49,8.41) v5(67.49,7.71) v5(67.49,7.01) v5(82.88,6.81) v5(82.88,5.79) v5(82.88,4.77) v5(83.9,6.81) v5(83.9,5.79) v5(83.9,4.77) v5(84.91,6.81) v5(84.91,5.79) v5(84.91,4.77) v5(99.77,6.81) v5(99.77,5.79) v5(100.79,6.81) v5(100.79,5.79) v5(101.8,6.81) v6(60.53,115.36) v6(61.55,117.39) v6(61.55,116.38) v6(61.55,115.36) v6(62.56,118.41) v6(62.56,116.38) v7(46.88,109.27) v7(46.88,107.27) v7(47.78,110.37) v7(47.78,106.17) v7(49.98,110.47) v7(49.98,106.07) v7(51.18,110.17) v7(51.18,106.37)
